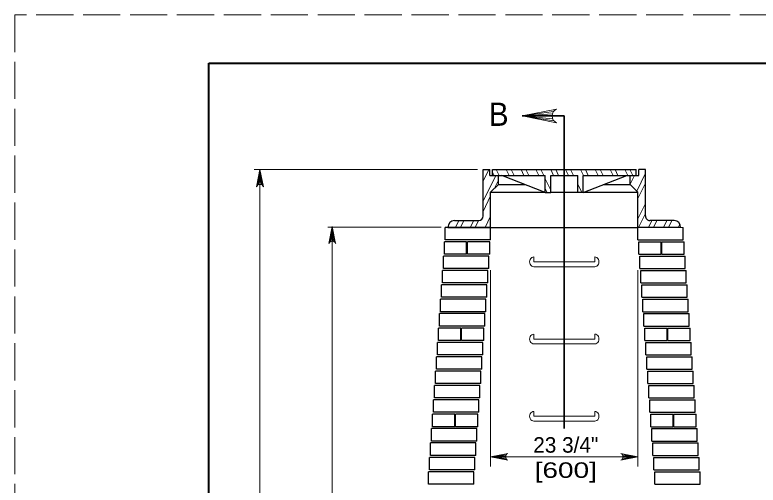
# Model space of a CAD drawing. Extents: x 750.7 to 784.7, y 860.1 to 882.1.
# Drawn here: x 750.65 to 758.32, y 877.27 to 882.12 of the extents above; entities that cross this region are included whole.
import ezdxf
from ezdxf.enums import TextEntityAlignment as Align

# ---------------------------------------------------------------- set-up
doc = ezdxf.new("R2010")
doc.units = 0
doc.header["$LTSCALE"] = 0.064
doc.linetypes.add('LONG_DASHED', pattern=[7.5, 6, -1.5])
doc.layers.add('1', color=7, linetype='Continuous', lineweight=13)

msp = doc.modelspace()

# ---------------------------------------------------------------- linework, layer by layer
at = {"layer": '1', "lineweight": 25}
for p, q in [((752.65083, 881.61842), (784.15083, 881.61842)), ((755.48142, 880.0445), (755.48142, 880.522)), ((755.48142, 880.522), (755.54967, 880.522)), ((755.54967, 880.46075), (755.54967, 880.522)), ((755.57842, 880.46075), (755.57842, 880.522)), ((755.57842, 880.522), (757.05892, 880.522)), ((757.05892, 880.46075), (757.05892, 880.522)), ((757.08767, 880.46075), (757.08767, 880.522)), ((757.15592, 880.522), (757.08767, 880.522)), ((757.15592, 880.0445), (757.15592, 880.522)), ((755.54967, 880.46075), (756.12275, 880.46075)), ((755.63875, 880.36667), (755.63867, 880.46075)), ((756.12275, 880.28658), (755.67483, 880.46075)), ((756.12275, 880.28658), (756.12275, 880.46075)), ((756.18025, 880.28617), (756.18025, 880.46075)), ((756.18025, 880.46075), (756.45708, 880.46075)), ((756.45708, 880.28617), (756.45708, 880.46075)), ((756.5145, 880.28658), (756.5145, 880.46075)), ((756.5145, 880.46075), (757.08767, 880.46075)), ((756.5145, 880.28658), (756.9625, 880.46075)), ((756.99858, 880.36667), (756.99858, 880.46075)), ((755.55925, 880.2885), (755.63875, 880.36667)), ((755.63875, 880.36667), (755.91667, 880.36667)), ((756.72067, 880.36667), (756.99858, 880.36667)), ((757.07808, 880.2885), (756.99858, 880.36667)), ((755.55925, 879.92525), (755.55925, 880.2885)), ((755.55925, 880.2885), (756.11775, 880.2885)), ((756.12275, 880.28658), (756.18025, 880.28617)), ((756.45708, 880.28617), (756.18025, 880.28617)), ((756.5145, 880.28658), (756.45708, 880.28617)), ((756.5195, 880.2885), (757.07808, 880.2885)), ((755.18492, 879.99625), (755.43608, 879.99625)), ((757.45242, 879.99625), (757.20117, 879.99625)), ((755.11833, 879.92525), (757.07808, 879.92525)), ((757.07808, 879.79725), (757.07808, 879.92525)), ((755.08133, 879.64892), (755.08133, 879.777)), ((755.31883, 879.649), (755.31883, 879.777)), ((757.31842, 879.649), (757.31842, 879.777)), ((757.556, 879.64892), (757.556, 879.777)), ((755.31142, 879.64892), (755.08133, 879.64892)), ((755.549, 879.649), (755.31883, 879.649)), ((757.08833, 879.649), (757.31842, 879.649)), ((757.32592, 879.64892), (757.556, 879.64892)), ((755.01975, 878.75933), (755.01975, 878.88742)), ((755.25733, 878.75933), (755.25733, 878.88742)), ((757.38, 878.75933), (757.38, 878.88742)), ((757.61758, 878.75933), (757.6175, 878.88742)), ((755.24992, 878.75933), (755.01975, 878.75933)), ((755.48742, 878.75933), (755.25733, 878.75933)), ((757.14983, 878.75933), (757.38, 878.75933)), ((757.38742, 878.75933), (757.61758, 878.75933)), ((754.95825, 877.86975), (754.95825, 877.99783)), ((755.19575, 877.86975), (755.19575, 877.99783)), ((757.4415, 877.86975), (757.4415, 877.99783)), ((757.67908, 877.86975), (757.67908, 877.99783)), ((755.18833, 877.86975), (754.95825, 877.86975)), ((755.42592, 877.86975), (755.19575, 877.86975)), ((757.21142, 877.86975), (757.4415, 877.86975)), ((757.44892, 877.86975), (757.67908, 877.86975))]:
    msp.add_line(p, q, dxfattribs=at)
at = {"layer": '1'}
for p, q in [((756.20642, 881.12108), (755.88583, 881.07625)), ((756.19558, 881.09892), (755.88583, 881.07625)), ((756.19225, 881.07625), (755.88583, 881.07625)), ((756.19792, 881.04742), (755.88583, 881.07625)), ((756.21017, 881.02667), (755.88583, 881.07625)), ((755.4225, 880.52275), (753.12075, 880.52275)), ((753.15492, 880.36067), (753.17967, 880.52283)), ((753.16525, 880.36683), (753.17967, 880.52283)), ((753.17967, 870.91333), (753.17967, 880.52283)), ((753.17967, 880.36967), (753.17967, 880.52283)), ((753.191, 880.368), (753.17967, 880.52283)), ((753.20208, 880.36258), (753.17967, 880.52283)), ((755.48142, 880.40408), (755.53908, 880.522)), ((755.48142, 880.5085), (755.488, 880.522)), ((755.59575, 880.46075), (755.57842, 880.49625)), ((755.64683, 880.46075), (755.61683, 880.522)), ((755.6585, 880.522), (755.99267, 880.522)), ((755.749, 880.46075), (755.719, 880.522)), ((755.80008, 880.46075), (755.77008, 880.522)), ((755.90225, 880.46075), (755.87225, 880.522)), ((755.95333, 880.46075), (755.92333, 880.522)), ((756.0255, 880.522), (756.0555, 880.46075)), ((756.10658, 880.46075), (756.07658, 880.522)), ((756.20875, 880.46075), (756.17875, 880.522)), ((756.25983, 880.46075), (756.22983, 880.522)), ((756.362, 880.46075), (756.332, 880.522)), ((756.41308, 880.46075), (756.38308, 880.522)), ((756.51525, 880.46075), (756.48525, 880.522)), ((756.56633, 880.46075), (756.53633, 880.522)), ((756.6685, 880.46075), (756.6385, 880.522)), ((756.71958, 880.46075), (756.68958, 880.522)), ((756.82175, 880.46075), (756.79175, 880.522)), ((756.87283, 880.46075), (756.84283, 880.522)), ((756.975, 880.46075), (756.945, 880.522)), ((757.026, 880.46075), (756.99608, 880.522)), ((757.0655, 880.30083), (757.15592, 880.48567)), ((755.48142, 880.19533), (755.61125, 880.46075)), ((755.59558, 880.32417), (755.63875, 880.41242)), ((756.18025, 880.31017), (756.12275, 880.42767)), ((756.99858, 880.373), (757.04158, 880.46075)), ((756.49833, 880.28642), (756.45708, 880.37083)), ((757.07808, 880.22217), (757.15592, 880.38125)), ((756.12275, 880.32325), (756.14075, 880.28642)), ((755.48142, 880.09092), (755.55925, 880.25)), ((757.07808, 880.01342), (757.15592, 880.1725)), ((755.5025, 879.92525), (755.55925, 880.04125)), ((757.086, 879.92525), (757.15592, 880.06808)), ((755.196, 879.92525), (755.23075, 879.99625)), ((755.24708, 879.92525), (755.28183, 879.99625)), ((755.34925, 879.92525), (755.384, 879.99625)), ((755.40033, 879.92525), (755.43508, 879.99625)), ((757.18817, 879.92525), (757.22292, 879.99625)), ((757.23925, 879.92525), (757.274, 879.99625)), ((757.34142, 879.92525), (757.37617, 879.99625)), ((757.3925, 879.92525), (757.42725, 879.99625)), ((757.49467, 879.92525), (757.51108, 879.95875)), ((755.047, 879.92833), (753.88025, 879.92833)), ((753.90008, 879.77333), (753.92483, 879.9355)), ((753.91042, 879.7795), (753.92483, 879.9355)), ((753.92483, 873.18092), (753.92483, 879.9355)), ((753.92483, 879.78233), (753.92483, 879.9355)), ((753.93617, 879.78067), (753.92483, 879.9355)), ((753.94725, 879.77525), (753.92483, 879.9355)), ((755.55358, 879.92525), (755.55925, 879.93683)), ((757.07808, 879.92525), (757.54575, 879.92525)), ((756.00417, 879.57067), (756.00417, 879.62075)), ((756.00417, 879.57067), (756.63317, 879.57067)), ((756.63317, 879.57067), (756.63308, 879.62075)), ((756.00417, 879.5205), (756.63317, 879.5205)), ((755.55925, 879.48325), (755.55925, 877.46033)), ((757.07808, 879.48325), (757.07808, 877.46033)), ((756.00417, 878.77408), (756.00417, 878.82417)), ((756.63317, 878.77408), (756.63308, 878.82417)), ((756.00417, 878.77408), (756.63317, 878.77408)), ((756.00417, 878.72392), (756.63317, 878.72392)), ((756.00417, 877.9775), (756.00417, 878.02758)), ((756.63317, 877.9775), (756.63308, 878.02758)), ((756.00417, 877.9775), (756.63317, 877.9775)), ((756.00417, 877.92733), (756.63317, 877.92733)), ((755.71958, 877.58058), (755.55925, 877.55817)), ((755.71417, 877.5695), (755.55925, 877.55817)), ((756.91775, 877.58058), (757.07808, 877.55817)), ((756.92317, 877.5695), (757.07808, 877.55817)), ((755.7125, 877.55817), (755.55925, 877.55817)), ((755.71533, 877.54375), (755.55925, 877.55817)), ((755.72142, 877.53342), (755.55925, 877.55817)), ((755.55925, 877.55817), (757.07808, 877.55817)), ((756.91583, 877.53342), (757.07808, 877.55817)), ((756.922, 877.54375), (757.07808, 877.55817)), ((756.92483, 877.55817), (757.07808, 877.55817))]:
    msp.add_line(p, q, dxfattribs=at)
at = {"layer": '1', "lineweight": 35}
for p, q in [((756.31867, 881.07625), (755.88583, 881.07625)), ((756.31867, 877.85167), (756.31867, 881.07625))]:
    msp.add_line(p, q, dxfattribs=at)
at = {"layer": '1', "linetype": 'LONG_DASHED'}
msp.add_lwpolyline([(750.65083, 860.11842), (784.65083, 860.11842), (784.65083, 882.11842), (750.65083, 882.11842)], close=True, dxfattribs=at)
at = {"layer": '1', "lineweight": 25}
for points in [[(784.15083, 860.61842), (752.65083, 860.61842), (752.65083, 881.61842)], [(757.51892, 879.92525), (757.07808, 879.92525), (757.07808, 880.2885)], [(755.55925, 879.79725), (755.55925, 879.92525), (755.09158, 879.92525)], [(755.55925, 879.79725), (755.09158, 879.79725), (755.09158, 879.92525)], [(757.07808, 879.79725), (757.54575, 879.79725), (757.54575, 879.92525)], [(755.31142, 879.64892), (755.31142, 879.777), (755.08133, 879.777)], [(755.549, 879.649), (755.549, 879.777), (755.31883, 879.777)], [(757.08833, 879.649), (757.08833, 879.777), (757.31842, 879.777)], [(757.32592, 879.64892), (757.32592, 879.777), (757.556, 879.777)], [(755.53875, 879.50067), (755.53875, 879.62875), (755.07108, 879.62875)], [(755.53875, 879.50067), (755.07108, 879.50067), (755.07108, 879.62875)], [(757.09858, 879.50067), (757.09858, 879.62875), (757.56625, 879.62875)], [(757.09858, 879.50067), (757.56625, 879.50067), (757.56625, 879.62875)], [(755.5285, 879.35242), (755.5285, 879.4805), (755.06083, 879.4805)], [(755.5285, 879.35242), (755.06083, 879.35242), (755.06083, 879.4805)], [(757.10883, 879.35242), (757.10883, 879.4805), (757.5765, 879.4805)], [(757.10883, 879.35242), (757.5765, 879.35242), (757.5765, 879.4805)], [(755.51825, 879.20417), (755.51825, 879.33225), (755.0505, 879.33225)], [(755.51825, 879.20417), (755.0505, 879.20417), (755.0505, 879.33225)], [(757.11908, 879.20417), (757.11908, 879.33225), (757.58675, 879.33225)], [(757.11908, 879.20417), (757.58675, 879.20417), (757.58675, 879.33225)], [(755.508, 879.05592), (755.508, 879.18392), (755.04025, 879.18392)], [(755.508, 879.05592), (755.04025, 879.05592), (755.04025, 879.18392)], [(757.12933, 879.05592), (757.12933, 879.18392), (757.597, 879.18392)], [(757.12933, 879.05592), (757.597, 879.05592), (757.597, 879.18392)], [(755.49767, 878.90767), (755.49767, 879.03567), (755.03, 879.03567)], [(755.49767, 878.90767), (755.03, 878.90767), (755.03, 879.03567)], [(757.13958, 878.90767), (757.13958, 879.03567), (757.60725, 879.03567)], [(757.13958, 878.90767), (757.60725, 878.90767), (757.60725, 879.03567)], [(755.24992, 878.75933), (755.24992, 878.88742), (755.01975, 878.88742)], [(755.48742, 878.75933), (755.48742, 878.88742), (755.25733, 878.88742)], [(757.14983, 878.75933), (757.14983, 878.88742), (757.38, 878.88742)], [(757.38742, 878.75933), (757.38742, 878.88742), (757.6175, 878.88742)], [(755.47717, 878.61108), (755.47717, 878.73917), (755.0095, 878.73917)], [(755.47717, 878.61108), (755.0095, 878.61108), (755.0095, 878.73917)], [(757.16008, 878.61108), (757.16008, 878.73917), (757.62783, 878.73917)], [(757.16008, 878.61108), (757.62783, 878.61108), (757.62783, 878.73917)], [(755.46692, 878.46283), (755.46692, 878.59092), (754.99925, 878.59092)], [(755.46692, 878.46283), (754.99925, 878.46283), (754.99925, 878.59092)], [(757.17033, 878.46283), (757.17033, 878.59092), (757.63808, 878.59092)], [(757.17033, 878.46283), (757.63808, 878.46283), (757.63808, 878.59092)], [(755.45667, 878.31458), (755.45667, 878.44258), (754.989, 878.44258)], [(755.45667, 878.31458), (754.989, 878.31458), (754.989, 878.44258)], [(757.18067, 878.31458), (757.18067, 878.44258), (757.64833, 878.44258)], [(757.18067, 878.31458), (757.64833, 878.31458), (757.64833, 878.44258)], [(755.44642, 878.16633), (755.44642, 878.29433), (754.97875, 878.29433)], [(755.44642, 878.16633), (754.97875, 878.16633), (754.97875, 878.29433)], [(757.19092, 878.16633), (757.19092, 878.29433), (757.65858, 878.29433)], [(757.19092, 878.16633), (757.65858, 878.16633), (757.65858, 878.29433)], [(755.43617, 878.018), (755.43617, 878.14608), (754.9685, 878.14608)], [(755.43617, 878.018), (754.9685, 878.018), (754.9685, 878.14608)], [(757.20117, 878.018), (757.20117, 878.14608), (757.66883, 878.14608)], [(757.20117, 878.018), (757.66883, 878.018), (757.66883, 878.14608)], [(755.18833, 877.86975), (755.18833, 877.99783), (754.95825, 877.99783)], [(755.42592, 877.86975), (755.42592, 877.99783), (755.19575, 877.99783)], [(757.21142, 877.86975), (757.21142, 877.99783), (757.4415, 877.99783)], [(757.44892, 877.86975), (757.44892, 877.99783), (757.67908, 877.99783)], [(755.41567, 877.7215), (755.41567, 877.84958), (754.948, 877.84958)], [(755.41567, 877.7215), (754.948, 877.7215), (754.948, 877.84958)], [(757.22167, 877.7215), (757.22167, 877.84958), (757.68933, 877.84958)], [(757.22167, 877.7215), (757.68933, 877.7215), (757.68933, 877.84958)], [(755.40542, 877.57325), (755.40542, 877.70133), (754.93775, 877.70133)], [(755.40542, 877.57325), (754.93775, 877.57325), (754.93775, 877.70133)], [(757.23192, 877.57325), (757.23192, 877.70133), (757.69958, 877.70133)], [(757.23192, 877.57325), (757.69958, 877.57325), (757.69958, 877.70133)], [(755.39517, 877.425), (755.39517, 877.553), (754.92742, 877.553)], [(755.39517, 877.425), (754.92742, 877.425), (754.92742, 877.553)], [(757.24217, 877.425), (757.24217, 877.553), (757.70983, 877.553)], [(757.24217, 877.425), (757.70983, 877.425), (757.70983, 877.553)], [(755.38492, 877.27667), (755.38492, 877.40475), (754.91717, 877.40475)], [(755.38492, 877.27667), (754.91717, 877.27667), (754.91717, 877.40475)], [(757.25242, 877.27667), (757.25242, 877.40475), (757.72008, 877.40475)], [(757.25242, 877.27667), (757.72008, 877.27667), (757.72008, 877.40475)]]:
    msp.add_lwpolyline(points, dxfattribs=at)
at = {"layer": '1', "lineweight": 40}
msp.add_lwpolyline([(752.65083, 881.61842), (784.15083, 881.61842), (784.15083, 860.61842), (752.65083, 860.61842)], close=True, dxfattribs=at)
at = {"layer": '1'}
for points in [[(756.23992, 881.00542), (755.88583, 881.07625), (756.23992, 881.14708)], [(753.14425, 880.34575), (753.17967, 880.52283), (753.21508, 880.34575)], [(753.88942, 879.7585), (753.92483, 879.9355), (753.96025, 879.7585)], [(755.73633, 877.52275), (755.55925, 877.55817), (755.73633, 877.59358)], [(756.901, 877.52275), (757.07808, 877.55817), (756.901, 877.59358)]]:
    msp.add_lwpolyline(points, dxfattribs=at)
for centre, radius, start, end in [((756.26855, 881.0763), 0.07644, 112.08782, 247.91395), ((753.17967, 880.33148), 0.03822, 22.08782, 157.91395), ((753.92489, 879.74416), 0.03822, 22.08782, 157.91395), ((755.75062, 877.55822), 0.03822, 112.08782, 247.91395), ((756.88668, 877.55822), 0.03822, 292.08605, 67.91218)]:
    msp.add_arc(centre, radius, start, end, dxfattribs=at)
at = {"layer": '1', "lineweight": 25}
for centre, major_axis, start_param, end_param in [((755.43611, 880.04454), (0, 0.04829), 3.1415937, 4.7123879), ((757.2012, 880.04453), (0, 0.04829), 1.5707963, 3.1415948), ((755.18491, 879.92529), (0, 0.07096), 0.0000048, 1.5708011), ((757.4524, 879.92529), (0, 0.07096), 4.7123842, 6.2831805)]:
    msp.add_ellipse(centre, major_axis=major_axis, ratio=0.937912, start_param=start_param, end_param=end_param, dxfattribs=at)
at = {"layer": '1'}
for centre, major_axis, end_param in [((756.00413, 879.57063), (0, 0.05012), 3.1415958), ((756.63317, 879.57063), (0, -0.05012), 3.143156), ((756.00413, 878.77404), (0, 0.05012), 3.1415958), ((756.63317, 878.77404), (0, -0.05012), 3.143156), ((756.00413, 877.97746), (0, 0.05012), 3.1415958), ((756.63317, 877.97746), (0, -0.05012), 3.143156)]:
    msp.add_ellipse(centre, major_axis=major_axis, ratio=0.869565, start_param=0.000003, end_param=end_param, dxfattribs=at)

# ---------------------------------------------------------------- texts
at = {"layer": '1', "width": 0.95}
msp.add_text('B', height=0.24, dxfattribs=at).set_placement((755.541, 880.97325))
at = {"layer": '1'}
msp.add_text('23 3/4"', height=0.16, dxfattribs=at).set_placement((756.33408, 877.6015), align=Align.CENTER)
at = {"layer": '1', "width": 1.35}
msp.add_text('[600]', height=0.16, dxfattribs=at).set_placement((756.33408, 877.3415), align=Align.CENTER)

doc.saveas('drawing.dxf')
